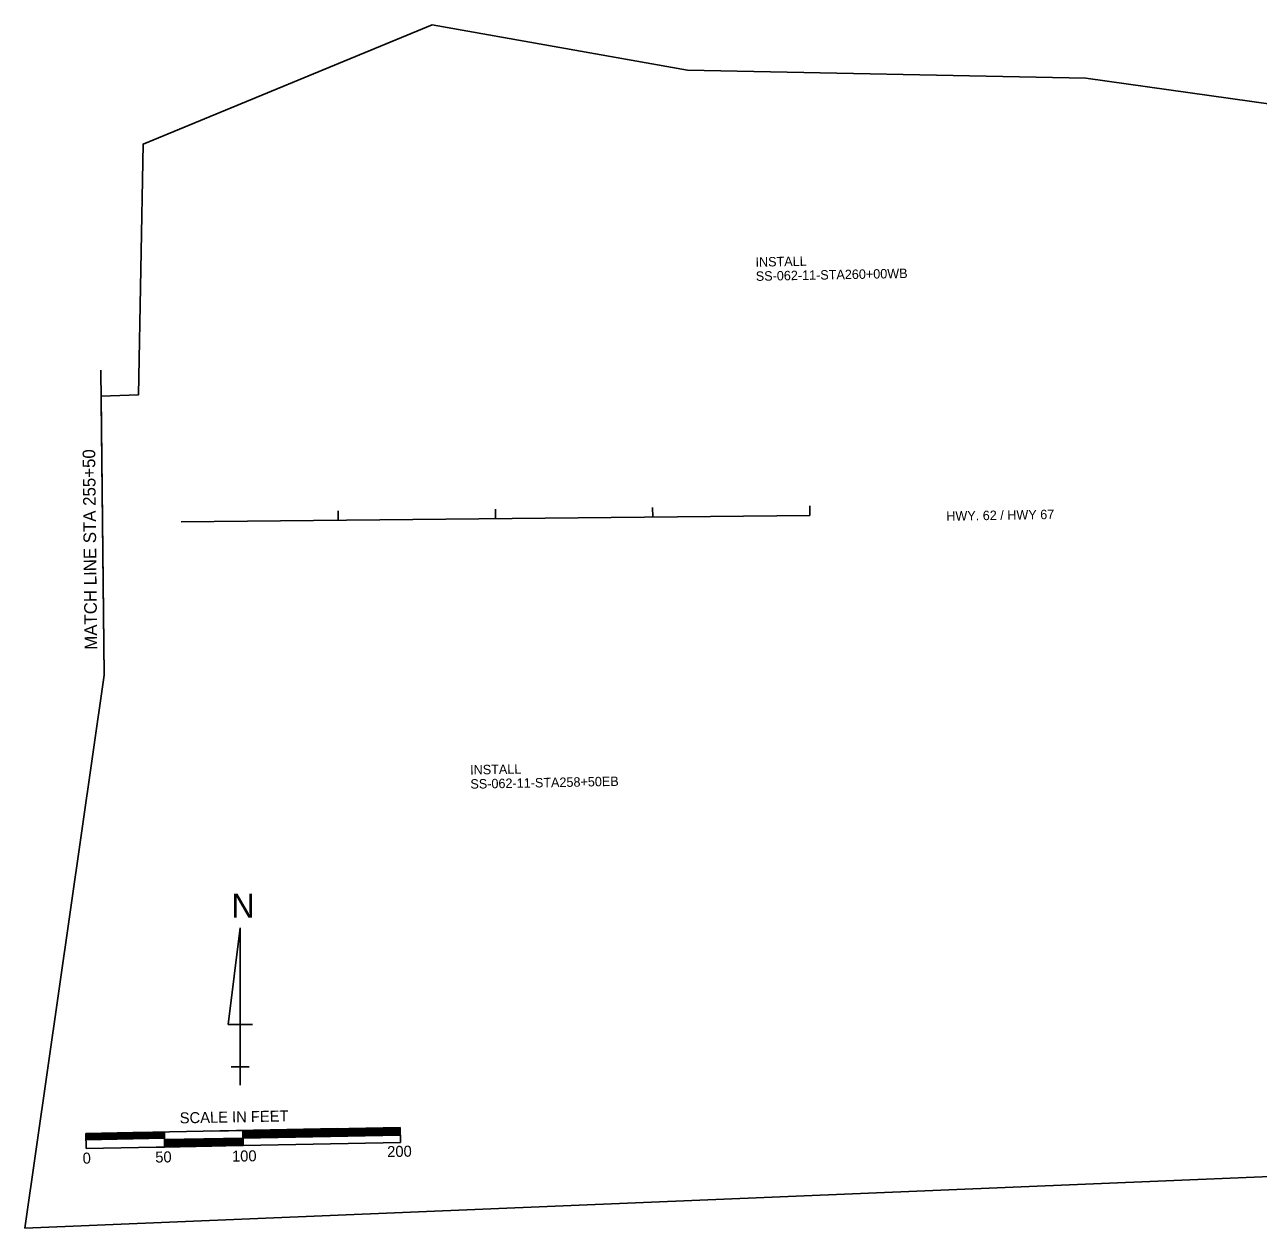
# Model space of a CAD drawing. Extents: x 1714319 to 1715889, y 758820 to 759853.
# Drawn here: x 1714319 to 1715104, y 758820 to 759585 of the extents above; entities that cross this region are included whole.
import ezdxf

# ---------------------------------------------------------------- set-up
doc = ezdxf.new("R2010")
doc.units = 0
for name, color, linetype in [('1', 7, 'Continuous'), ('63', 7, 'Continuous'), ('Level 10', 7, 'Continuous'), ('Plan Notes', 7, 'Continuous'), ('R_Annotation', 7, 'Continuous'), ('R_Draft', 7, 'Continuous'), ('R_Horz Alg', 7, 'Continuous'), ('R_Horz Alg Stationing', 7, 'Continuous')]:
    doc.layers.add(name, color=color, linetype=linetype)

msp = doc.modelspace()

# ---------------------------------------------------------------- linework, layer by layer
at = {"layer": '1'}
msp.add_lwpolyline([(1714319.22, 758819.84), (1714369.71, 759171.73), (1714367.88, 759349.11), (1714391.54, 759349.9), (1714394.5, 759509.48), (1714578.32, 759585.44), (1714740.71, 759556.57), (1714994.15, 759551.37), (1715258.12, 759514.35), (1715744.07, 759581.73), (1715827.43, 759379.47), (1715830.72, 759207.18), (1715867.87, 758884.19)], close=True, dxfattribs=at)
at = {"layer": '63'}
for p, q in [((1714456.34, 759010.94), (1714448.64, 758949.4)), ((1714456.34, 758910.94), (1714456.34, 759010.94)), ((1714456.34, 759010.94), (1714456.34, 758934.02)), ((1714448.64, 758949.4), (1714464.03, 758949.4)), ((1714456.34, 758910.94), (1714456.34, 758934.02)), ((1714456.34, 758922.48), (1714450.57, 758922.48)), ((1714450.57, 758922.48), (1714462.11, 758922.48)), ((1714456.34, 758910.94), (1714456.34, 758922.48))]:
    msp.add_line(p, q, dxfattribs=at)
at = {"layer": 'Level 10'}
for p, q in [((1714358.08, 758880.19), (1714518.05, 758883.24)), ((1714358.08, 758880.19), (1714398.07, 758880.95)), ((1714358.26, 758870.59), (1714358.08, 758880.19)), ((1714358.09, 758879.39), (1714408.08, 758880.34)), ((1714358.11, 758878.59), (1714408.1, 758879.54)), ((1714358.12, 758877.79), (1714408.11, 758878.75)), ((1714408.25, 758871.54), (1714408.07, 758881.14)), ((1714438.06, 758881.71), (1714558.04, 758884)), ((1714458.24, 758872.49), (1714458.06, 758882.08)), ((1714458.08, 758881.29), (1714558.06, 758883.2)), ((1714458.09, 758880.49), (1714558.07, 758882.4)), ((1714458.11, 758879.7), (1714558.09, 758881.6)), ((1714458.12, 758878.89), (1714558.1, 758880.8)), ((1714458.14, 758878.1), (1714558.12, 758880)), ((1714458.15, 758877.29), (1714558.13, 758879.2)), ((1714558.22, 758874.38), (1714558.04, 758883.98)), ((1714358.14, 758876.99), (1714408.13, 758877.94)), ((1714358.15, 758876.19), (1714408.15, 758877.15)), ((1714358.26, 758870.59), (1714558.22, 758874.4)), ((1714398.25, 758871.35), (1714438.25, 758872.11)), ((1714408.16, 758876.34), (1714458.15, 758877.29)), ((1714408.18, 758875.54), (1714458.17, 758876.5)), ((1714408.19, 758874.74), (1714458.18, 758875.7)), ((1714408.21, 758873.94), (1714458.2, 758874.9)), ((1714408.22, 758873.14), (1714458.21, 758874.1)), ((1714408.24, 758872.34), (1714458.23, 758873.3)), ((1714458.15, 758877.29), (1714518.14, 758878.44))]:
    msp.add_line(p, q, dxfattribs=at)
at = {"layer": 'Plan Notes'}
msp.add_line((1714369.71, 759171.73), (1714367.71, 759365.66), dxfattribs=at)
at = {"layer": 'R_Horz Alg'}
msp.add_line((1714418.7, 759269.21), (1714818.68, 759273.34), dxfattribs=at)
at = {"layer": 'R_Horz Alg Stationing'}
for p, q in [((1714818.62, 759279.34), (1714818.68, 759273.34)), ((1714518.64, 759276.24), (1714518.7, 759270.24)), ((1714618.63, 759277.28), (1714618.69, 759271.28)), ((1714718.63, 759278.31), (1714718.69, 759272.31))]:
    msp.add_line(p, q, dxfattribs=at)

# ---------------------------------------------------------------- texts
at = {"layer": '63'}
msp.add_text('N', height=15.38, rotation=360, dxfattribs=at).set_placement((1714450.7, 759017.35))
at = {"layer": 'Level 10'}
for s, height, p in [('SCALE IN FEET', 7.0007, (1714417.9, 758886.56)), ('200', 7.001, (1714549.87, 758865.15)), ('0', 7, (1714356.17, 758860.94)), ('50', 7.001, (1714402.35, 758861.63)), ('100', 7.001, (1714451.16, 758862.21))]:
    msp.add_text(s, height=height, rotation=1.09194, dxfattribs=at).set_placement(p)
at = {"layer": 'Plan Notes'}
msp.add_text('MATCH LINE STA 255+50', height=8, rotation=90.59167, dxfattribs=at).set_placement((1714365.37, 759187.89))
at = {"layer": 'R_Annotation'}
for s, p in [('INSTALL', (1714784.12, 759431.48)), ('SS-062-11-STA260+00WB', (1714784.3, 759422.48)), ('INSTALL', (1714602.61, 759108.46)), ('SS-062-11-STA258+50EB', (1714602.78, 759099.46))]:
    msp.add_text(s, height=6, rotation=1.09167, dxfattribs=at).set_placement(p)
at = {"layer": 'R_Draft'}
msp.add_text('HWY. 62 / HWY 67', height=6, rotation=0.94393, dxfattribs=at).set_placement((1714905.47, 759269.88))

doc.saveas('drawing.dxf')
